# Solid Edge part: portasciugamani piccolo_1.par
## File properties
Last saved by: i.fialdini
Revision: 62
Tipo di contenuto documento: 0
Accuracy: 0.990
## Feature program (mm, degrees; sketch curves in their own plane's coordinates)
body "unnamed Body 1"
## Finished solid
Body 1: solid body, 10 faces, 24 edges, 16 vertices.
  Faces by surface: plane 7, cylinder 3
  Edges by curve: line 18, circle 6
Bounding box of the edges (mm): 45.000 x 386.500 x 2.000, from (-238.5, -210, -147) to (-193.5, 176.5, -145).
Cylindrical faces by radius (mm): R5 x2, R33.5 x1
Planar faces by outward normal: +x 2, +y 1, +z 1, -x 2, -z 1
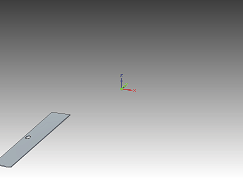
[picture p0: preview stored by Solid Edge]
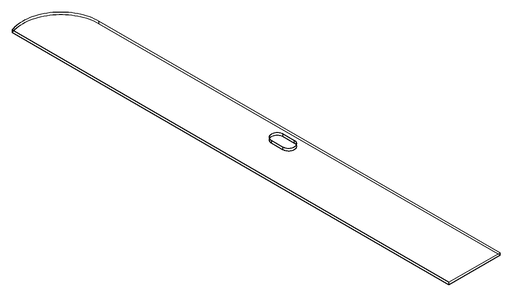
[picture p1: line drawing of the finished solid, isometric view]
